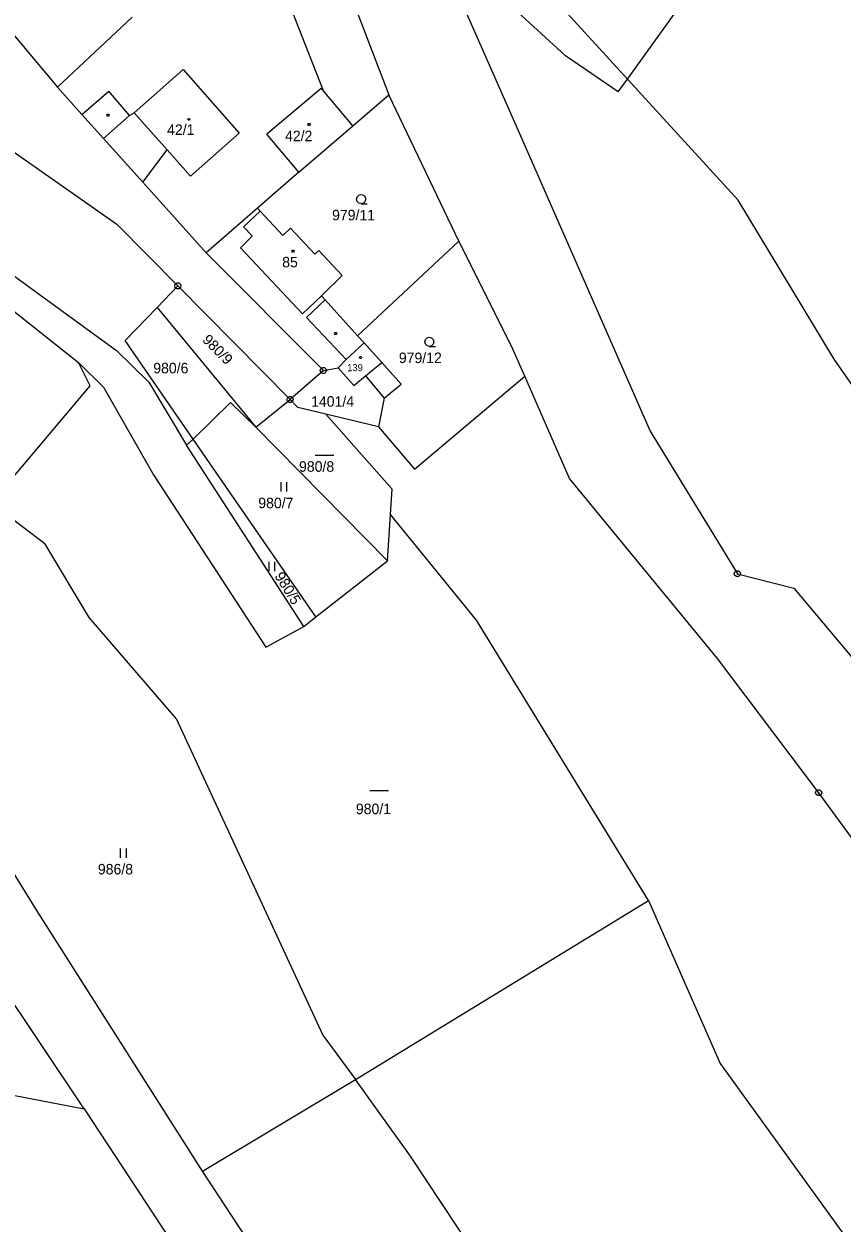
# Model space of a CAD drawing. Extents: x -850689 to -847910, y -1058374 to -1054747.
# Drawn here: x -849114.6 to -848982.2, y -1056444.2 to -1056250.1 of the extents above; entities that cross this region are included whole.
import ezdxf

# ---------------------------------------------------------------- set-up
doc = ezdxf.new("R2010")
doc.units = 0
for name, color, linetype in [('KN_HRANICE', 7, 'Continuous'), ('KN_KULTURY', 7, 'Continuous'), ('KN_MEZNIKY', 7, 'Continuous'), ('KN_PARCELY', 7, 'Continuous'), ('KN_SLUCKY', 7, 'Continuous'), ('KN_STAVEBNI', 7, 'Continuous')]:
    doc.layers.add(name, color=color, linetype=linetype)

# ---------------------------------------------------------------- blocks, each defined once
blk = doc.blocks.new('304')
blk.add_lwpolyline([(0, 0), (-0.38, 0.1), (-0.65, 0.37), (-0.75, 0.74), (-0.65, 1.11), (-0.38, 1.38), (-0.01, 1.48), (0.36, 1.38), (0.63, 1.11), (0.73, 0.73), (0.63, 0.35), (0.36, 0.08), (-0.02, -0.02), (0.98, -0.02)])
blk = doc.blocks.new('306')
for p, q in [((-0.5, 1.5), (-0.5, 0)), ((0.5, 0), (0.5, 1.5))]:
    blk.add_line(p, q)
blk = doc.blocks.new('804')
blk.add_line((-1.5, 0), (1.5, 0))
blk = doc.blocks.new('402')
blk.add_lwpolyline([(0.09, 0.15), (0.18, 0), (0.09, -0.15), (-0.09, -0.15), (-0.18, 0), (-0.09, 0.15), (0.09, 0.15)])
blk = doc.blocks.new('105')
blk.add_line((-0.12, 0), (0.12, 0))
blk.add_lwpolyline([(0.15, 0.48), (0.4, 0.3), (0.5, 0.01), (0.4, -0.28), (0.15, -0.46), (-0.16, -0.46), (-0.41, -0.28), (-0.51, 0.01), (-0.41, 0.3), (-0.16, 0.48), (0.15, 0.48)])

msp = doc.modelspace()

# ---------------------------------------------------------------- linework, layer by layer
at = {"layer": 'KN_HRANICE'}
for p, q in [((-849051.11, -1056229.98), (-849034.65, -1056267.35)), ((-849016.97, -1056259.04), (-848998.88, -1056233.84)), ((-849063.18, -1056241.7), (-849055.56, -1056261.61)), ((-849026.95, -1056255.29), (-849041.27, -1056242.15)), ((-849123.4, -1056243.38), (-849109.14, -1056260.33)), ((-849029.32, -1056245.51), (-849016.97, -1056259.04)), ((-849071.44, -1056247.58), (-849066.2, -1056260.88)), ((-849109.14, -1056260.33), (-849097.09, -1056249.01)), ((-849018.45, -1056261.11), (-849026.95, -1056255.29)), ((-849088.84, -1056257.51), (-849096.74, -1056264.5)), ((-849088.84, -1056257.51), (-849079.77, -1056267.77)), ((-849132.64, -1056259.34), (-849099.56, -1056282.53)), ((-849018.45, -1056261.11), (-849016.97, -1056259.04)), ((-849016.97, -1056259.04), (-848999.06, -1056278.65)), ((-849105.2, -1056264.76), (-849109.14, -1056260.33)), ((-849105.2, -1056264.76), (-849100.84, -1056260.97)), ((-849097.53, -1056264.92), (-849100.84, -1056260.97)), ((-849066.49, -1056260.54), (-849075.28, -1056267.94)), ((-849066.2, -1056260.88), (-849066.49, -1056260.54)), ((-849061.38, -1056266.6), (-849066.2, -1056260.88)), ((-849061.38, -1056266.6), (-849055.56, -1056261.61)), ((-849044.22, -1056285.28), (-849055.56, -1056261.61)), ((-849101.7, -1056268.66), (-849105.2, -1056264.76)), ((-849097.53, -1056264.92), (-849096.74, -1056264.5)), ((-849079.77, -1056267.77), (-849087.67, -1056274.76)), ((-849070.1, -1056274.09), (-849061.38, -1056266.6)), ((-849034.65, -1056267.35), (-849013.3, -1056316.04)), ((-849095.37, -1056275.7), (-849101.7, -1056268.66)), ((-849070.1, -1056274.09), (-849075.28, -1056267.94)), ((-849095.37, -1056275.7), (-849091.44, -1056270.5)), ((-849087.67, -1056274.76), (-849091.44, -1056270.5)), ((-849070.1, -1056274.09), (-849076.82, -1056279.93)), ((-849085.1, -1056287.14), (-849095.37, -1056275.7)), ((-848983.5, -1056304.39), (-848999.06, -1056278.65)), ((-849076.82, -1056279.93), (-849085.1, -1056287.14)), ((-849076.82, -1056279.93), (-849076.38, -1056280.44)), ((-849076.38, -1056280.44), (-849072.72, -1056284.35)), ((-849099.56, -1056282.53), (-849089.69, -1056292.52)), ((-849072.72, -1056284.35), (-849071.45, -1056283.16)), ((-849071.45, -1056283.16), (-849067.51, -1056287.35)), ((-849060.61, -1056300.57), (-849044.22, -1056285.28)), ((-849035.65, -1056302.35), (-849044.22, -1056285.28)), ((-849085.1, -1056287.14), (-849066.14, -1056306.21)), ((-849067.51, -1056287.35), (-849066.89, -1056286.77)), ((-849066.89, -1056286.77), (-849063.1, -1056290.8)), ((-849119.35, -1056288.63), (-849099.62, -1056302.96)), ((-849063.1, -1056290.8), (-849066.44, -1056294.11)), ((-849093.06, -1056296.02), (-849089.69, -1056292.52)), ((-849089.69, -1056292.52), (-849071.52, -1056310.9)), ((-849120.55, -1056293.17), (-849105.79, -1056304.92)), ((-849065.87, -1056294.74), (-849066.44, -1056294.11)), ((-849060.61, -1056300.57), (-849065.87, -1056294.74)), ((-849098.21, -1056301.36), (-849093.06, -1056296.02)), ((-849093.06, -1056296.02), (-849077.08, -1056315.37)), ((-849059.57, -1056301.72), (-849060.61, -1056300.57)), ((-849087.23, -1056317.3), (-849098.21, -1056301.36)), ((-849062.46, -1056304.42), (-849059.57, -1056301.72)), ((-849056.7, -1056304.89), (-849059.57, -1056301.72)), ((-849033.57, -1056307.12), (-849035.65, -1056302.35)), ((-849099.62, -1056302.96), (-849094.39, -1056308.08)), ((-849063.74, -1056305.76), (-849062.46, -1056304.42)), ((-848967.17, -1056327.9), (-848983.5, -1056304.39)), ((-849103.9, -1056308.71), (-849105.79, -1056304.92)), ((-849105.79, -1056304.92), (-849101.71, -1056308.92)), ((-849066.14, -1056306.21), (-849071.52, -1056310.9)), ((-849066.14, -1056306.21), (-849063.74, -1056305.76)), ((-849063.74, -1056305.76), (-849061.22, -1056308.64)), ((-849053.54, -1056308.4), (-849056.7, -1056304.89)), ((-849094.39, -1056308.08), (-849088.27, -1056318.26)), ((-849061.22, -1056308.64), (-849059.32, -1056307.07)), ((-849059.32, -1056307.07), (-849056.31, -1056310.7)), ((-849056.31, -1056310.7), (-849053.54, -1056308.4)), ((-849051.42, -1056322.16), (-849033.57, -1056307.12)), ((-849026.35, -1056323.66), (-849033.57, -1056307.12)), ((-849119.84, -1056327.63), (-849103.9, -1056308.71)), ((-849101.71, -1056308.92), (-849093.63, -1056323.1)), ((-849081.17, -1056311.38), (-849087.23, -1056317.3)), ((-849077.08, -1056315.37), (-849081.17, -1056311.38)), ((-849077.08, -1056315.37), (-849071.52, -1056310.9)), ((-849071.52, -1056310.9), (-849070.27, -1056312.21)), ((-849065.77, -1056313.28), (-849070.27, -1056312.21)), ((-849056.31, -1056310.7), (-849057.24, -1056315.32)), ((-849057.24, -1056315.32), (-849065.77, -1056313.28)), ((-849065.77, -1056313.28), (-849055.03, -1056325.42)), ((-849077.08, -1056315.37), (-849055.79, -1056337.03)), ((-849057.24, -1056315.32), (-849051.42, -1056322.16)), ((-849013.3, -1056316.04), (-848999.16, -1056339.1)), ((-849088.27, -1056318.26), (-849087.23, -1056317.3)), ((-849069.32, -1056347.66), (-849088.27, -1056318.26)), ((-849067.39, -1056346.09), (-849087.23, -1056317.3)), ((-849093.63, -1056323.1), (-849075.46, -1056350.96)), ((-849002.37, -1056352.82), (-849026.35, -1056323.66)), ((-849055.3, -1056329.49), (-849055.03, -1056325.42)), ((-849119.84, -1056327.63), (-849111.2, -1056334.22)), ((-849055.79, -1056337.03), (-849055.3, -1056329.49)), ((-849041.37, -1056346.6), (-849055.3, -1056329.49)), ((-849104.06, -1056346.16), (-849111.2, -1056334.22)), ((-849067.39, -1056346.09), (-849055.79, -1056337.03)), ((-848999.16, -1056339.1), (-848990.06, -1056341.42)), ((-848990.06, -1056341.42), (-848946.95, -1056392.82)), ((-849089.97, -1056362.5), (-849104.06, -1056346.16)), ((-849069.32, -1056347.66), (-849067.39, -1056346.09)), ((-849013.53, -1056391.99), (-849041.37, -1056346.6)), ((-849075.46, -1056350.96), (-849069.32, -1056347.66)), ((-849112.51, -1056393.58), (-849139.79, -1056349.71)), ((-848986.01, -1056374.55), (-849002.37, -1056352.82)), ((-849089.97, -1056362.5), (-849066.26, -1056413.75)), ((-848960.15, -1056409.91), (-848986.01, -1056374.55)), ((-849060.94, -1056420.96), (-849013.53, -1056391.99)), ((-849013.53, -1056391.99), (-849001.93, -1056418.36)), ((-849085.71, -1056435.76), (-849112.51, -1056393.58)), ((-849104.83, -1056425.71), (-849122.42, -1056399.43)), ((-849066.26, -1056413.75), (-849060.94, -1056420.96)), ((-849139.78, -1056418.98), (-849104.83, -1056425.71)), ((-849001.93, -1056418.36), (-848977.76, -1056451.81)), ((-849085.71, -1056435.76), (-849060.94, -1056420.96)), ((-849052.06, -1056433.36), (-849060.94, -1056420.96)), ((-849104.83, -1056425.71), (-849077.96, -1056466.55)), ((-849017.3, -1056485.72), (-849052.06, -1056433.36)), ((-849068.63, -1056461.72), (-849085.71, -1056435.76))]:
    msp.add_line(p, q, dxfattribs=at)
at = {"layer": 'KN_SLUCKY'}
for p, q in [((-849097.53, -1056264.92), (-849101.7, -1056268.66)), ((-849091.44, -1056270.5), (-849096.74, -1056264.5)), ((-849079.06, -1056282.95), (-849076.38, -1056280.44)), ((-849078.61, -1056283.42), (-849079.06, -1056282.95)), ((-849079.55, -1056286.37), (-849077.65, -1056284.44)), ((-849077.65, -1056284.44), (-849078.61, -1056283.42)), ((-849069.52, -1056297.01), (-849079.55, -1056286.37)), ((-849066.44, -1056294.11), (-849069.52, -1056297.01)), ((-849068.9, -1056297.62), (-849065.87, -1056294.74)), ((-849062.46, -1056304.42), (-849068.9, -1056297.62)), ((-849059.32, -1056307.07), (-849056.7, -1056304.89))]:
    msp.add_line(p, q, dxfattribs=at)
at = {"layer": 'KN_STAVEBNI'}
for p, q in [((-849088.84, -1056257.51), (-849096.74, -1056264.5)), ((-849088.84, -1056257.51), (-849079.77, -1056267.77)), ((-849066.49, -1056260.54), (-849075.28, -1056267.94)), ((-849066.2, -1056260.88), (-849066.49, -1056260.54)), ((-849061.38, -1056266.6), (-849066.2, -1056260.88)), ((-849091.44, -1056270.5), (-849096.74, -1056264.5)), ((-849079.77, -1056267.77), (-849087.67, -1056274.76)), ((-849070.1, -1056274.09), (-849061.38, -1056266.6)), ((-849070.1, -1056274.09), (-849075.28, -1056267.94)), ((-849087.67, -1056274.76), (-849091.44, -1056270.5)), ((-849079.06, -1056282.95), (-849076.38, -1056280.44)), ((-849076.38, -1056280.44), (-849072.72, -1056284.35)), ((-849078.61, -1056283.42), (-849079.06, -1056282.95)), ((-849072.72, -1056284.35), (-849071.45, -1056283.16)), ((-849071.45, -1056283.16), (-849067.51, -1056287.35)), ((-849079.55, -1056286.37), (-849077.65, -1056284.44)), ((-849077.65, -1056284.44), (-849078.61, -1056283.42)), ((-849069.52, -1056297.01), (-849079.55, -1056286.37)), ((-849067.51, -1056287.35), (-849066.89, -1056286.77)), ((-849066.89, -1056286.77), (-849063.1, -1056290.8)), ((-849063.1, -1056290.8), (-849066.44, -1056294.11)), ((-849066.44, -1056294.11), (-849069.52, -1056297.01)), ((-849062.46, -1056304.42), (-849059.57, -1056301.72)), ((-849056.7, -1056304.89), (-849059.57, -1056301.72)), ((-849063.74, -1056305.76), (-849062.46, -1056304.42)), ((-849063.74, -1056305.76), (-849061.22, -1056308.64)), ((-849059.32, -1056307.07), (-849056.7, -1056304.89)), ((-849061.22, -1056308.64), (-849059.32, -1056307.07))]:
    msp.add_line(p, q, dxfattribs=at)

# ---------------------------------------------------------------- block references
at = {"layer": 'KN_KULTURY'}
for name, p in [('402', (-849101, -1056264.89)), ('402', (-849087.92, -1056265.56)), ('402', (-849068.46, -1056266.38)), ('304', (-849060.04, -1056279.2)), ('402', (-849071.07, -1056286.9)), ('402', (-849064.17, -1056300.21)), ('304', (-849049, -1056302.3)), ('402', (-849060.14, -1056304.1)), ('804', (-849065.96, -1056319.89)), ('306', (-849072.55, -1056325.79)), ('306', (-849074.49, -1056338.69)), ('804', (-849057.13, -1056374.15)), ('306', (-849098.5, -1056385.06))]:
    msp.add_blockref(name, p, dxfattribs=at)
at = {"layer": 'KN_MEZNIKY'}
for p in [(-849089.69, -1056292.52), (-849066.14, -1056306.21), (-849071.52, -1056310.9), (-848999.16, -1056339.1), (-848986.01, -1056374.55)]:
    msp.add_blockref('105', p, dxfattribs=at)

# ---------------------------------------------------------------- texts
at = {"layer": 'KN_PARCELY'}
for s, height, p in [('42/1', 1.7, (-849091.43, -1056268.07)), ('42/2', 1.7, (-849072.35, -1056269.09)), ('979/11', 1.7, (-849064.74, -1056281.9)), ('85', 1.7, (-849072.81, -1056289.51)), ('979/12', 1.7, (-849053.94, -1056305)), ('980/6', 1.7, (-849093.67, -1056306.66)), ('139', 1.14, (-849062.3, -1056306.31)), ('1401/4', 1.7, (-849068.13, -1056312.06)), ('980/8', 1.7, (-849070.09, -1056322.59)), ('980/7', 1.7, (-849076.68, -1056328.49)), ('980/1', 1.7, (-849060.89, -1056378)), ('986/8', 1.7, (-849102.63, -1056387.76))]:
    msp.add_text(s, height=height, dxfattribs=at).set_placement(p)
for s, rotation, p in [('980/9', 314.783, (-849085.85, -1056301.37)), ('980/5', 302.121, (-849074.12, -1056339.47))]:
    msp.add_text(s, height=1.7, rotation=rotation, dxfattribs=at).set_placement(p)

doc.saveas('drawing.dxf')
